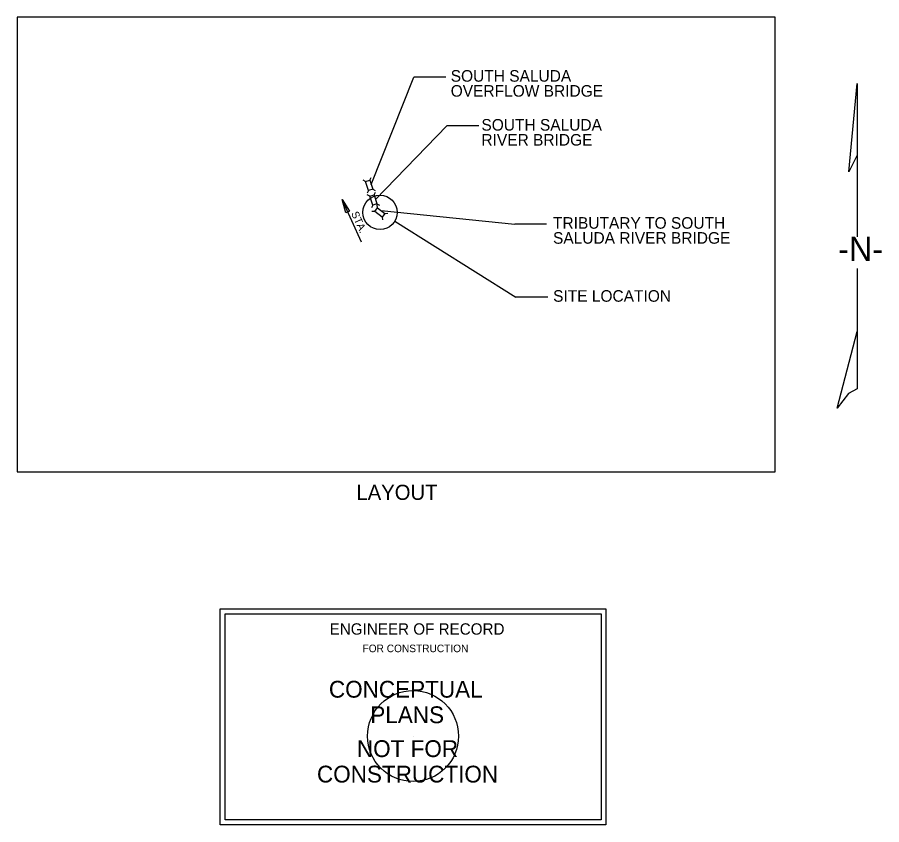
# Model space of a CAD drawing. Extents: x 0 to 4.15, y -2.5 to 1.79.
# Drawn here: x 2.958 to 4.146, y 0.058 to 1.169 of the extents above; entities that cross this region are included whole.
import ezdxf

# ---------------------------------------------------------------- set-up
doc = ezdxf.new("R2010")
doc.units = 0
for name, color, linetype in [('BR_AUTO DIMENSION', 7, 'Continuous'), ('BR_BORDER LINES', 7, 'Continuous'), ('BR_DETAILS', 7, 'Continuous'), ('BR_TEXT', 7, 'Continuous'), ('Default', 7, 'Continuous'), ('NoPlot', 7, 'Continuous')]:
    doc.layers.add(name, color=color, linetype=linetype)

msp = doc.modelspace()

# ---------------------------------------------------------------- linework, layer by layer
at = {"layer": 'BR_AUTO DIMENSION'}
for p, q in [((3.4449, 0.9387), (3.5034, 1.0863)), ((3.5472, 1.0863), (3.5034, 1.0863)), ((3.4507, 0.9184), (3.5488, 1.0197)), ((3.5926, 1.0197), (3.5488, 1.0197)), ((3.4584, 0.9029), (3.642, 0.8844)), ((3.4772, 0.8884), (3.6435, 0.784)), ((3.6858, 0.8844), (3.642, 0.8844)), ((3.6873, 0.784), (3.6435, 0.784))]:
    msp.add_line(p, q, dxfattribs=at)
msp.add_circle((3.4569, 0.9004), 0.0236, dxfattribs=at)
at = {"layer": 'BR_BORDER LINES'}
msp.add_lwpolyline([(2.9583, 0.5438), (4, 0.5438), (4, 1.1688), (2.9583, 1.1688)], close=True, dxfattribs=at)
at = {"layer": 'BR_DETAILS'}
for points in [[(3.2372, 0.3551), (3.7672, 0.3551), (3.7672, 0.0585), (3.2372, 0.0585)], [(3.2439, 0.3485), (3.7606, 0.3485), (3.7606, 0.0651), (3.2439, 0.0651)]]:
    msp.add_lwpolyline(points, close=True, dxfattribs=at)
at = {"layer": 'BR_TEXT'}
for p, q in [((3.4371, 0.9429), (3.4335, 0.9448)), ((3.4429, 0.9447), (3.4447, 0.9484)), ((3.441, 0.9307), (3.4392, 0.927)), ((3.4469, 0.9326), (3.4504, 0.9306)), ((3.4487, 0.9245), (3.4505, 0.9282)), ((3.4313, 0.8594), (3.4048, 0.918)), ((3.4428, 0.9226), (3.4393, 0.9245)), ((3.4468, 0.9104), (3.445, 0.9068)), ((3.4526, 0.9123), (3.4562, 0.9104)), ((3.4533, 0.9068), (3.4527, 0.9108)), ((3.4496, 0.9019), (3.4455, 0.9015)), ((3.4597, 0.8941), (3.4603, 0.8901)), ((3.4635, 0.899), (3.4675, 0.8994))]:
    msp.add_line(p, q, dxfattribs=at)
for points in [[(3.4469, 0.9326), (3.441, 0.9307), (3.4371, 0.9429), (3.4429, 0.9447)], [(3.4099, 0.8998), (3.4048, 0.918), (3.415, 0.9021)], [(3.4526, 0.9123), (3.4468, 0.9104), (3.4428, 0.9226), (3.4487, 0.9245)], [(3.4635, 0.899), (3.4597, 0.8941), (3.4496, 0.9019), (3.4533, 0.9068)]]:
    msp.add_lwpolyline(points, close=True, dxfattribs=at)
at = {"layer": 'Default'}
for p, q in [((4.1013, 0.9564), (4.1124, 1.0778)), ((4.1124, 1.0778), (4.1124, 0.979)), ((4.1124, 0.979), (4.1013, 0.9564)), ((4.1124, 0.979), (4.1124, 0.9105)), ((4.1124, 0.9105), (4.1124, 0.8668)), ((4.1124, 0.8232), (4.1124, 0.7369)), ((4.0849, 0.6311), (4.1124, 0.7369)), ((4.1124, 0.7369), (4.1124, 0.7238)), ((4.1124, 0.7238), (4.1124, 0.6577))]:
    msp.add_line(p, q, dxfattribs=at)
msp.add_lwpolyline([(4.1124, 0.6577), (4.1006, 0.6512), (4.0849, 0.6311)], dxfattribs=at)
at = {"layer": 'NoPlot'}
msp.add_line((3.5022, 0.1804), (3.5022, 0.1804), dxfattribs=at)
msp.add_circle((3.5022, 0.1804), 0.0625, dxfattribs=at)

# ---------------------------------------------------------------- texts
at = {"layer": 'BR_DETAILS'}
for s, height, p in [('CONCEPTUAL', 0.02311, (3.3866, 0.2332)), ('PLANS', 0.02311, (3.4435, 0.1981)), ('NOT FOR', 0.02311, (3.4251, 0.1515)), ('CONSTRUCTION', 0.023108, (3.3702, 0.1165))]:
    msp.add_text(s, height=height, rotation=360, dxfattribs=at).set_placement(p)
at = {"layer": 'BR_TEXT'}
for s, height, rotation, p in [('SOUTH SALUDA ', 0.015922, 360, (3.554, 1.0802)), ('OVERFLOW BRIDGE', 0.015922, 360, (3.554, 1.0596)), ('SOUTH SALUDA ', 0.015922, 360, (3.5962, 1.0129)), ('RIVER BRIDGE', 0.015922, 360, (3.5962, 0.9923)), ('STA.', 0.01042, 294.3217, (3.4169, 0.8991)), ('TRIBUTARY TO SOUTH ', 0.015922, 360, (3.6946, 0.878)), ('SALUDA RIVER BRIDGE', 0.015922, 360, (3.6946, 0.8574)), ('SITE LOCATION ', 0.015922, 360, (3.6947, 0.7776))]:
    msp.add_text(s, height=height, rotation=rotation, dxfattribs=at).set_placement(p)
at = {"layer": 'Default'}
for s, height, p in [('-N-', 0.03333, (4.0864, 0.8337)), ('LAYOUT', 0.02083, (3.4244, 0.5051)), ('ENGINEER OF RECORD', 0.015625, (3.3876, 0.3198)), ('FOR CONSTRUCTION', 0.010417, (3.4328, 0.2957))]:
    msp.add_text(s, height=height, dxfattribs=at).set_placement(p)

doc.saveas('drawing.dxf')
